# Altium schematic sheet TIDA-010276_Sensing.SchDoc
size 431 x 279 mm; Date: Not shown in title block; ApprovedBy: Not shown in title block; CheckedBy: Not shown in title block; Author: Not shown in title block; CompanyName: Not shown in title block; DrawnBy: Jenson Fang; Engineer: Jenson Fang; Organization: Not shown in title block; Address1: Not shown in title block; Address2: Not shown in title block; Address3: Not shown in title block; Address4: Not shown in title block; DocumentNumber: 1; Revision: Use project parameter SCH_Rev; SheetNumber: 4; SheetTotal: 6; PageSetup: Record=PageOptions¦CenterHorizontal=True¦CenterVertical=True¦PrintScale=1.00¦XCorrection=1.00¦YCorrection=1.00¦PrintKind=0¦BorderSize=5000000¦LeftOffset=0¦BottomOffset=0¦Orientation=2¦PaperLength=1000¦PaperWidth=1000¦Scale=100¦PaperSource=15¦PrintQuality=600¦MediaType=1¦DitherType=10¦PaperKind=Letter¦PrintScaleMode=1
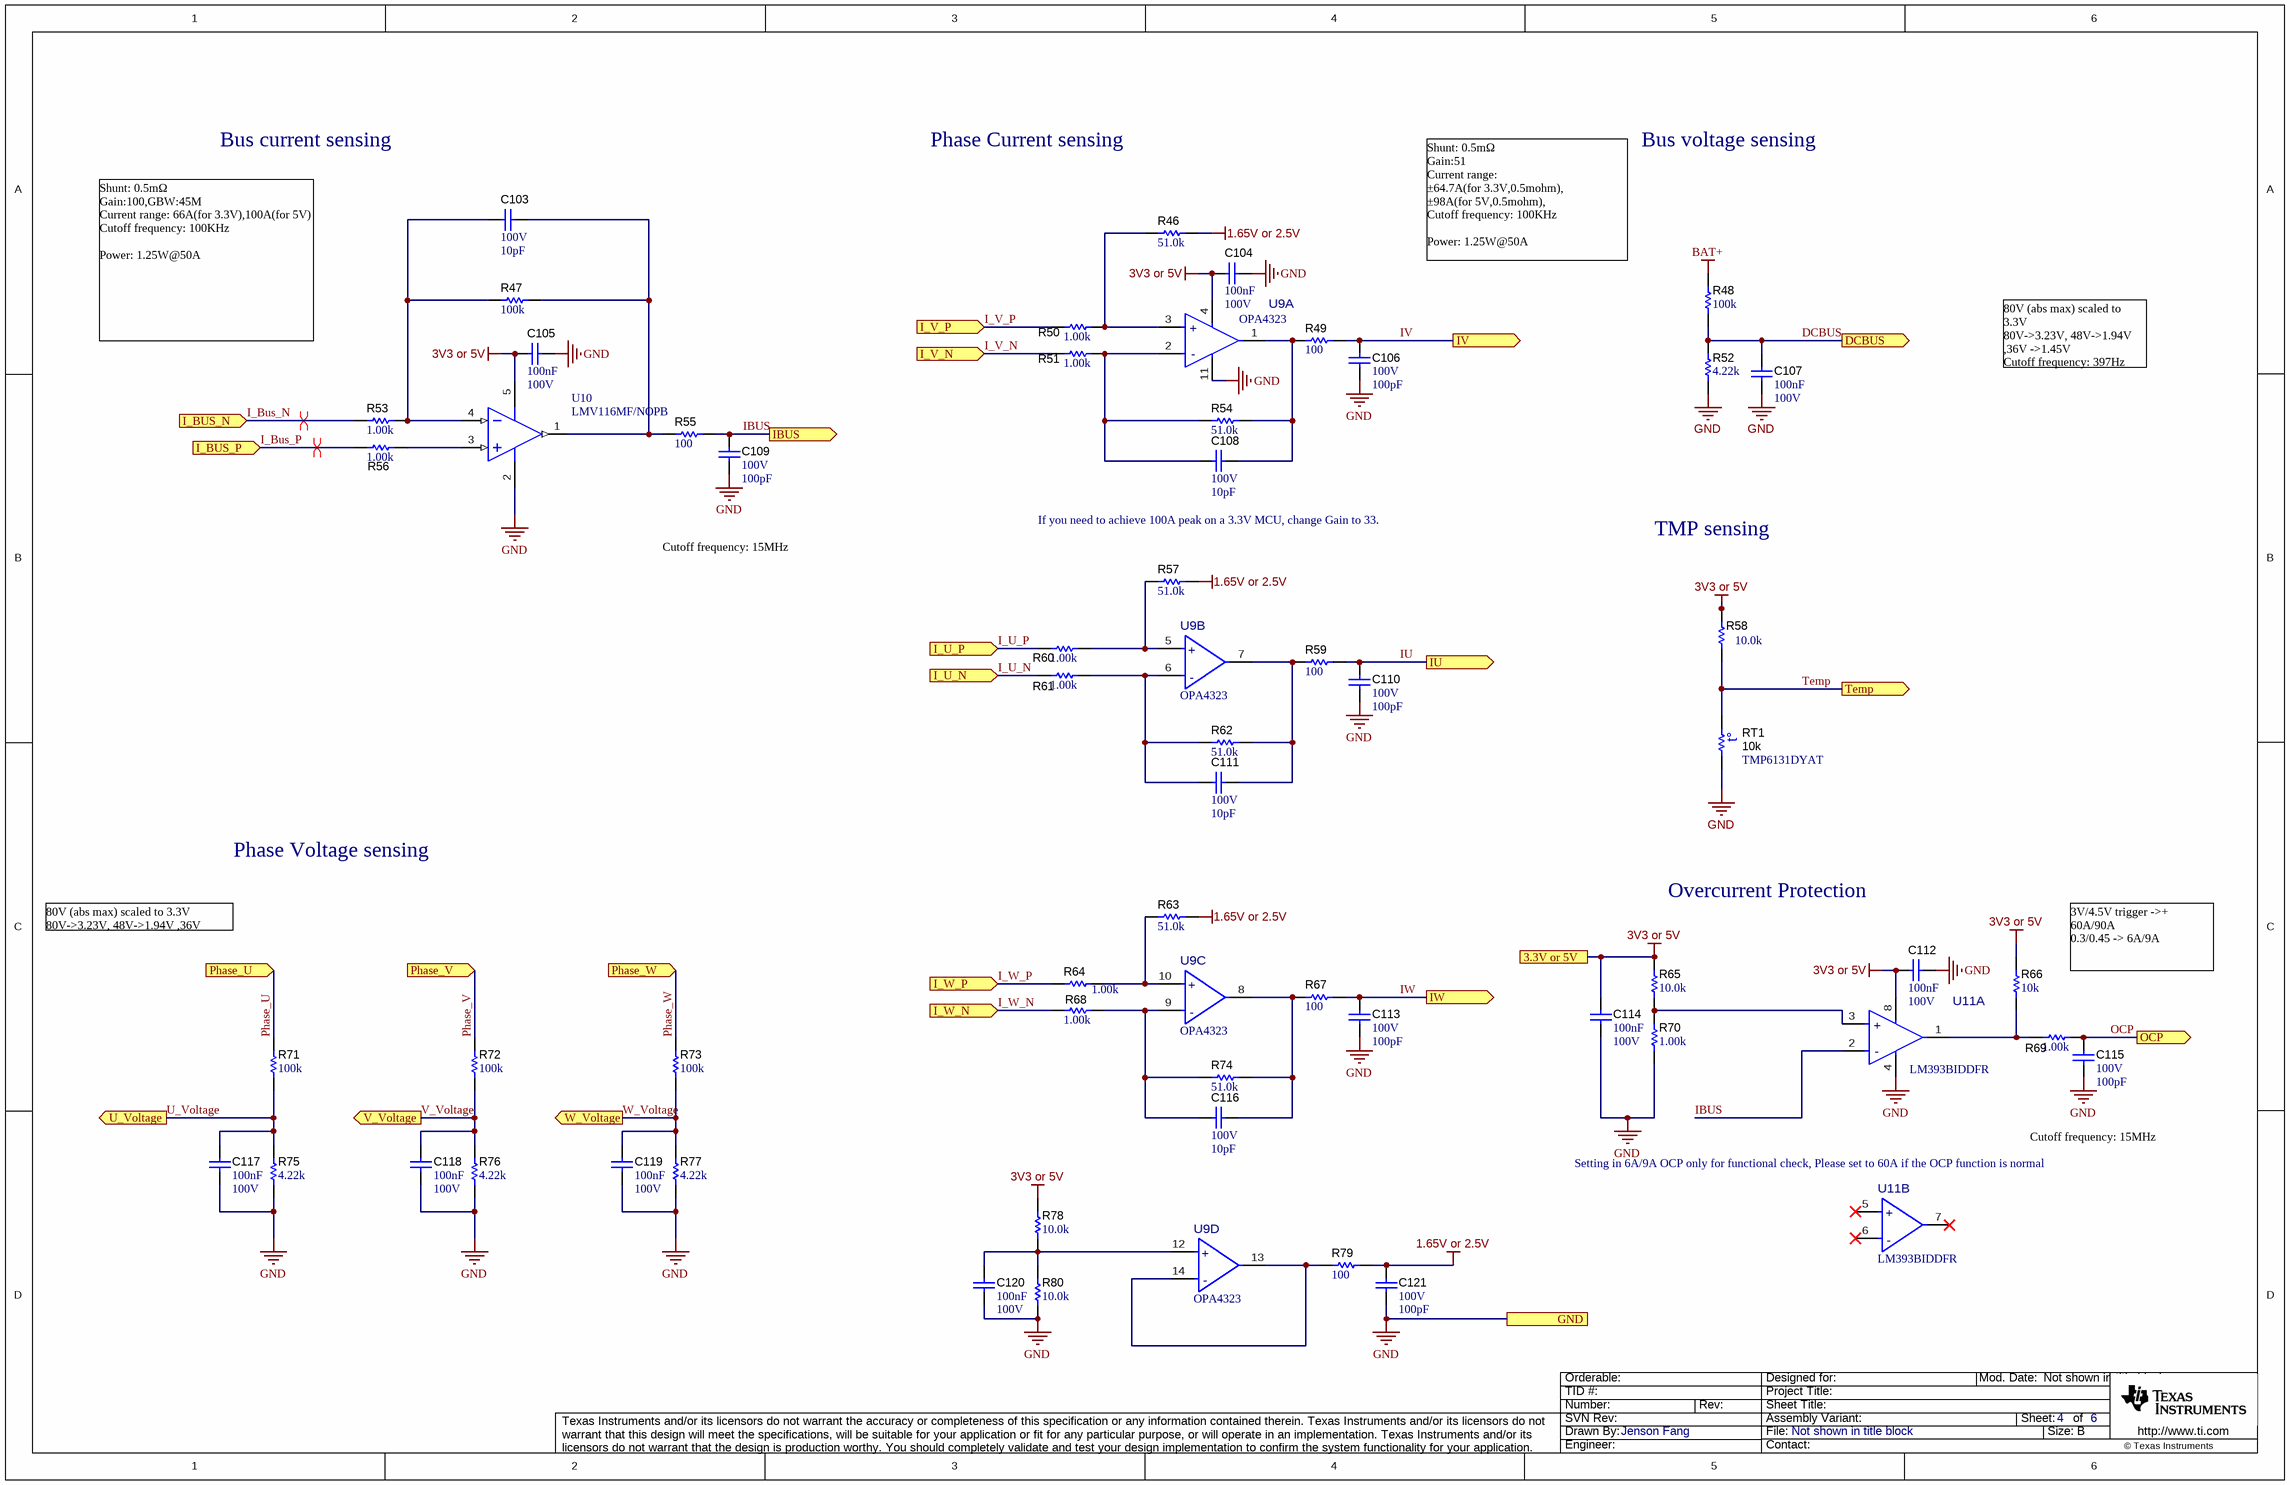
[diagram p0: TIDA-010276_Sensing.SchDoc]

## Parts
C103  VDC_V: 100V  ValueDisplayed: 10pF  [0603]  (hidden comment: GRM1885C2A100JA01D)
C104  Cap_F: 100nF  VDC_V: 100V  [0603]  (hidden comment: GRM188R72A104KA35D)
C105  Cap_F: 100nF  VDC_V: 100V  [0603]  (hidden comment: GRM188R72A104KA35D)
C106  VDC_V: 100V  ValueDisplayed: 100pF  [0603]  (hidden comment: GRM1885C2A101JA01D)
C107  Cap_F: 100nF  VDC_V: 100V  [0603]  (hidden comment: GRM188R72A104KA35D)
C108  VDC_V: 100V  ValueDisplayed: 10pF  [0603]  (hidden comment: GRM1885C2A100JA01D)
C109  VDC_V: 100V  ValueDisplayed: 100pF  [0603]  (hidden comment: GRM1885C2A101JA01D)
C110  VDC_V: 100V  ValueDisplayed: 100pF  [0603]  (hidden comment: GRM1885C2A101JA01D)
C111  VDC_V: 100V  ValueDisplayed: 10pF  [0603]  (hidden comment: GRM1885C2A100JA01D)
C112  Cap_F: 100nF  VDC_V: 100V  [0603]  (hidden comment: GRM188R72A104KA35D)
C113  VDC_V: 100V  ValueDisplayed: 100pF  [0603]  (hidden comment: GRM1885C2A101JA01D)
C114  Cap_F: 100nF  VDC_V: 100V  [0603]  (hidden comment: GRM188R72A104KA35D)
C115  VDC_V: 100V  ValueDisplayed: 100pF  [0603]  (hidden comment: GRM1885C2A101JA01D)
C116  VDC_V: 100V  ValueDisplayed: 10pF  [0603]  (hidden comment: GRM1885C2A100JA01D)
C117  Cap_F: 100nF  VDC_V: 100V  [0603]  (hidden comment: GRM188R72A104KA35D)
C118  Cap_F: 100nF  VDC_V: 100V  [0603]  (hidden comment: GRM188R72A104KA35D)
C119  Cap_F: 100nF  VDC_V: 100V  [0603]  (hidden comment: GRM188R72A104KA35D)
C120  Cap_F: 100nF  VDC_V: 100V  [0603]  (hidden comment: GRM188R72A104KA35D)
C121  VDC_V: 100V  ValueDisplayed: 100pF  [0603]  (hidden comment: GRM1885C2A101JA01D)
R46  ValueDisplayed: 51.0k  [0603]  (hidden comment: RC0603FR-0751KL)
R47  ValueDisplayed: 100k  [0603]  (hidden comment: CRCW0603100KJNEAC)
R48  ValueDisplayed: 100k  [0603]  (hidden comment: CRCW0603100KFKEA)
R49  ValueDisplayed: 100  [0603]  (hidden comment: CRCW0603100RFKEA)
R50  ValueDisplayed: 1.00k  [0603]  (hidden comment: CRCW06031K00FKEA)
R51  ValueDisplayed: 1.00k  [0603]  (hidden comment: CRCW06031K00FKEA)
R52  ValueDisplayed: 4.22k  [0603]  (hidden comment: RC0603FR-074K22L)
R53  ValueDisplayed: 1.00k  [0603]  (hidden comment: CRCW06031K00FKEA)
R54  ValueDisplayed: 51.0k  [0603]  (hidden comment: RC0603FR-0751KL)
R55  ValueDisplayed: 100  [0603]  (hidden comment: CRCW0603100RFKEA)
R56  ValueDisplayed: 1.00k  [0603]  (hidden comment: CRCW06031K00FKEA)
R57  ValueDisplayed: 51.0k  [0603]  (hidden comment: RC0603FR-0751KL)
R58  ValueDisplayed: 10.0k  [0603]  (hidden comment: CRCW060310K0FKEA)
R59  ValueDisplayed: 100  [0603]  (hidden comment: CRCW0603100RFKEA)
R60  ValueDisplayed: 1.00k  [0603]  (hidden comment: CRCW06031K00FKEA)
R61  ValueDisplayed: 1.00k  [0603]  (hidden comment: CRCW06031K00FKEA)
R62  ValueDisplayed: 51.0k  [0603]  (hidden comment: RC0603FR-0751KL)
R63  ValueDisplayed: 51.0k  [0603]  (hidden comment: RC0603FR-0751KL)
R64  ValueDisplayed: 1.00k  [0603]  (hidden comment: CRCW06031K00FKEA)
R65  ValueDisplayed: 10.0k  [0603]  (hidden comment: CRCW060310K0FKEA)
R66  ValueDisplayed: 10k  [0603]  (hidden comment: CRCW060310K0JNEA)
R67  ValueDisplayed: 100  [0603]  (hidden comment: CRCW0603100RFKEA)
R68  ValueDisplayed: 1.00k  [0603]  (hidden comment: CRCW06031K00FKEA)
R69  ValueDisplayed: 1.00k  [0603]  (hidden comment: CRCW06031K00FKEA)
R70  ValueDisplayed: 1.00k  [0603]  (hidden comment: CRCW06031K00FKEA)
R71  ValueDisplayed: 100k  [0603]  (hidden comment: CRCW0603100KFKEA)
R72  ValueDisplayed: 100k  [0603]  (hidden comment: CRCW0603100KFKEA)
R73  ValueDisplayed: 100k  [0603]  (hidden comment: CRCW0603100KFKEA)
R74  ValueDisplayed: 51.0k  [0603]  (hidden comment: RC0603FR-0751KL)
R75  ValueDisplayed: 4.22k  [0603]  (hidden comment: RC0603FR-074K22L)
R76  ValueDisplayed: 4.22k  [0603]  (hidden comment: RC0603FR-074K22L)
R77  ValueDisplayed: 4.22k  [0603]  (hidden comment: RC0603FR-074K22L)
R78  ValueDisplayed: 10.0k  [0603]  (hidden comment: CRCW060310K0FKEA)
R79  ValueDisplayed: 100  [0603]  (hidden comment: CRCW0603100RFKEA)
R80  ValueDisplayed: 10.0k  [0603]  (hidden comment: CRCW060310K0FKEA)
RT1  value 10k  [DYA0002A-MFG]  (hidden comment: TMP6131DYAT)
U9  OPA4323  [PW0014A-MFG]  (parts A,B,C,D of 4)
U10  LMV116MF/NOPB  [DBV0005A_N]
U11  LM393BIDDFR  [DDF0008A-MFG]  (parts A,B of 2)

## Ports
3.3V or 5V, DCBUS (out), GND, I_BUS_N (in), I_BUS_P (in), I_U_N (in), I_U_P (in), I_V_N (in), I_V_P (in), I_W_N (in), I_W_P (in), IBUS (out), IU (out), IV (out), IW (out), OCP (out), Phase_U (in), Phase_V (in), Phase_W (in), Temp (out), U_Voltage (out), V_Voltage (out), W_Voltage (out)

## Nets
1.65V or 2.5V: C121.1 R46.2 R57.2 R63.2 R79.2
3V3 or 5V: C104.2 C105.2 C112.2 C114.1 R58.2 R65.2 R66.2 R78.2 U9.4(V+) U10.5(V+) U11.8(VCC) ; port 3.3V or 5V
BAT+: R48.2
GND: C104.1 C105.1 C106.2 C107.2 C109.2 C110.2 C112.1 C113.2 C114.2 C115.2 C117.2 C118.2 C119.2 C120.2 C121.2 R52.1 R70.1 R75.1 R76.1 R77.1 R80.1 RT1.1 U9.11(V-) U10.2(V-) U11.4(GND) ; port GND
DCBUS: C107.1 R48.1 R52.2 ; port DCBUS
I_Bus_N: R53.1 ; port I_BUS_N
I_Bus_P: R56.1 ; port I_BUS_P
I_U_N: R61.2 ; port I_U_N
I_U_P: R60.1 ; port I_U_P
I_V_N: R51.1 ; port I_V_N
I_V_P: R50.1 ; port I_V_P
I_W_N: R68.1 ; port I_W_N
I_W_P: R64.1 ; port I_W_P
IBUS: C109.1 R55.2 U11.2(1IN-) ; port IBUS
IU: C110.1 R59.2 ; port IU
IV: C106.1 R49.2 ; port IV
IW: C113.1 R67.2 ; port IW
OCP: C115.1 R69.1 ; port OCP
Phase_U: R71.2 ; port Phase_U
Phase_V: R72.2 ; port Phase_V
Phase_W: R73.2 ; port Phase_W
Temp: R58.1 RT1.2 ; port Temp
U_Voltage: C117.1 R71.1 R75.2 ; port U_Voltage
V_Voltage: C118.1 R72.1 R76.2 ; port V_Voltage
W_Voltage: C119.1 R73.1 R77.2 ; port W_Voltage
NetC103_1: C103.1 R47.2 R55.1 U10.1(OUT)
NetC103_2: C103.2 R47.1 R53.2 U10.4(IN-)
NetC108_1: C108.1 R49.1 R54.2 U9.1(OUT1)
NetC108_2: C108.2 R51.2 R54.1 U9.2(IN1-)
NetC111_1: C111.1 R59.1 R62.2 U9.7(OUT2)
NetC111_2: C111.2 R61.1 R62.1 U9.6(IN2-)
NetC116_1: C116.1 R67.1 R74.2 U9.8(OUT3)
NetC116_2: C116.2 R68.2 R74.1 U9.9(IN3-)
NetC120_1: C120.1 R78.1 R80.2 U9.12(IN4+)
NetR46_1: R46.1 R50.2 U9.3(IN1+)
NetR56_2: R56.2 U10.3(IN+)
NetR57_1: R57.1 R60.2 U9.5(IN2+)
NetR63_1: R63.1 R64.2 U9.10(IN3+)
NetR65_1: R65.1 R70.2 U11.3(1IN+)
NetR66_1: R66.1 R69.2 U11.1(1OUT)
NetR79_1: R79.1 U9.13(IN4-) U9.14(OUT4)

Not connected (* = marked no-connect by the designer): U11 5(2IN+)* 6(2IN-)* 7(2OUT)*

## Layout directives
differential pair: I_Bus_N, I_Bus_P

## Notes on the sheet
- Bus current sensing
- Phase Current sensing
- Bus voltage sensing
- Shunt: 0.5mΩ
  Gain:51
  Current range:
  ±64.7A(for 3.3V,0.5mohm),
  ±98A(for 5V,0.5mohm),
  Cutoff frequency: 100KHz
  Power: 1.25W@50A
- Shunt: 0.5mΩ
  Gain:100,GBW:45M
  Current range: 66A(for 3.3V),100A(for 5V)
  Cutoff frequency: 100KHz
  Power: 1.25W@50A
- 80V (abs max) scaled to 3.3V
  80V->3.23V, 48V->1.94V ,36V ->1.45V
  Cutoff frequency: 397Hz
- Cutoff frequency: 15MHz
- If you need to achieve 100A peak on a 3.3V MCU, change Gain to 33.
- TMP sensing
- Phase Voltage sensing
- Overcurrent Protection
- 80V (abs max) scaled to 3.3V
  80V->3.23V, 48V->1.94V ,36V ->1.45V
  output= input voltage * Dudy * 0.0404
- 3V/4.5V trigger ->+ 60A/90A
  0.3/0.45 -> 6A/9A
- (near U11) Setting in 6A/9A OCP only for functional check, Please set to 60A if the OCP function is normal

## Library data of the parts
C103 C108 C111 C116 = CMP-0007236-3: CAP, CERM, 10 pF, 100 V, +/- 5%, C0G/NP0, 0603; Manufacturer: MuRata; TaMin_C: -55°C; Polarized: N; SizeAreaWB_mm2: 4.68; Value1: Unknown; U/M: EA; Value: 10pF; TaMax_C: 125°C; SizeZ_mm: 1; SizeX_mm: 1.6; SizeY_mm: 0.8; SizeArea_mm2: 1.28; AEC Category: Q200
C104 C105 C107 C112 C114 C117-C120 = CMP-0007469-4: CAP, CERM, 0.1 uF, 100 V, +/- 10%, X7R, 0603; Manufacturer: MuRata; TaMin_C: -55°C; Polarized: N; SizeAreaWB_mm2: 4.68; Value1: Unknown; U/M: EA; Value: 0.1uF; TaMax_C: 125°C; SizeZ_mm: 1; SizeX_mm: 1.6; SizeY_mm: 0.8; SizeArea_mm2: 1.28; AEC Category: Q200
C106 C109 C110 C113 C115 C121 = CMP-0007237-4: CAP, CERM, 100 pF, 100 V, +/- 5%, C0G/NP0, 0603; Manufacturer: MuRata; TaMin_C: -55°C; Polarized: N; SizeAreaWB_mm2: 4.68; Value1: Unknown; U/M: EA; Value: 100pF; TaMax_C: 125°C; SizeZ_mm: 1; SizeX_mm: 1.6; SizeY_mm: 0.8; SizeArea_mm2: 1.28; AEC Category: Q200
R46 R54 R57 R62 R63 R74 = CMP-0023167-5: RES, 51.0 k, 1%, 0.1 W, 0603; Manufacturer: Yageo; Power_W: 100mW; TempCo: 100 ppm/C; Value_Code: 51k0; Value: 51.0k; Res_ohm: 51k; SizeX_mm: 1.6; SizeY_mm: 0.8; SizeZ_mm: 1; Value2: 0.1W; SizeArea_mm2: 1.28; AEC Qualified: N; VDC_V: 75V; AEC Category: Q200; SizeAreaWB_mm2: 4.68
R47 = CMP-0082530-1: RES, 100 k, 5%, 0.1 W, 0603; Manufacturer: Vishay-Dale; Power_W: 100mW; TempCo: 200 ppm/C; SizeAreaWB_mm2: 4.68; Value: 100k; EIA_Code: E24; SizeX_mm: 1.6; SizeY_mm: 0.8; SizeZ_mm: 1; Value2: 0.1W; SizeArea_mm2: 1.28; AEC Qualified: N; VDC_V: 75V; AEC Category: Q200
R48 R71-R73 = CMP-0021990-1: RES, 100 k, 1%, 0.1 W, 0603; Manufacturer: Vishay-Dale; Power_W: 100mW; TempCo: 100 ppm/C; U/M: EA; Value: 100k; EIA_Code: E96; SizeX_mm: 1.6; SizeY_mm: 0.8; SizeZ_mm: 1; Value2: 0.1W; SizeArea_mm2: 1.28; VDC_V: 75V; AEC Category: Q200
R49 R55 R59 R67 R79 = CMP-0021991-4: RES, 100, 1%, 0.1 W, AEC-Q200 Grade 0, 0603; Manufacturer: Vishay-Dale; Power_W: 100mW; TempCo: 100 ppm/C; Value_Code: 100R; Value: 100; EIA_Code: E96; SizeX_mm: 1.6; SizeY_mm: 0.8; SizeZ_mm: 1; Value2: 0.1W; SizeArea_mm2: 1.28; AEC Qualified: Y; VDC_V: 75V; AEC Category: Q200; AEC Grade: 0
R50 R51 R53 R56 R60 R61 R64 R68-R70 = CMP-0022109-2: RES, 1.00 k, 1%, 0.1 W, 0603; Manufacturer: Vishay-Dale; Power_W: 100mW; TempCo: 100 ppm/C; Value_Code: 1k00; U/M: EA; Value: 1.00k; EIA_Code: E96; Res_ohm: 1k; SizeX_mm: 1.6; SizeY_mm: 0.8; SizeZ_mm: 1; Value2: 0.1W; SizeArea_mm2: 1.28; VDC_V: 75V; AEC Category: Q200
R52 R75-R77 = CMP-0023146-5: RES, 4.22 k, 1%, 0.1 W, 0603; Manufacturer: Yageo; Power_W: 100mW; TempCo: 100 ppm/C; Value_Code: 4k22; Value: 4.22k; EIA_Code: E96; SizeX_mm: 1.6; SizeY_mm: 0.8; SizeZ_mm: 1; Value2: 0.1W; SizeArea_mm2: 1.28; AEC Qualified: N; VDC_V: 75V; AEC Category: Q200; SizeAreaWB_mm2: 4.68
R58 R65 R78 R80 = CMP-0021998-2: RES, 10.0 k, 1%, 0.1 W, 0603; Manufacturer: Vishay-Dale; Power_W: 100mW; TempCo: 100 ppm/C; Value_Code: 10k0; U/M: EA; Value: 10.0k; EIA_Code: E96; Res_ohm: 10k; SizeX_mm: 1.6; SizeY_mm: 0.8; SizeZ_mm: 1; Value2: 0.1W; SizeArea_mm2: 1.28; VDC_V: 75V; AEC Category: Q200
R66 = CMP-0025701-4: RES, 10 k, 5%, 0.1 W, AEC-Q200 Grade 0, 0603; Manufacturer: Vishay-Dale; Power_W: 100mW; TempCo: 200 ppm/C; Value_Code: 10k0; Value: 10k; EIA_Code: E24; SizeX_mm: 1.6; SizeY_mm: 0.8; SizeZ_mm: 1; Value2: 0.1W; SizeArea_mm2: 1.28; AEC Qualified: Y; VDC_V: 75V; AEC Category: Q200; AEC Grade: 0
RT1 = CMP-0091865-2: ±1% tolerance 10kΩ linear thermistor available in 0402 and 0603 package options 2-SOT-5X3 -40 to 125; Manufacturer: Texas Instruments; Max Current: 400uA; AEC Qualified: No; TJmax_C: +155°C; TaMin_C: -40°C; TempCo: 6400ppm/°C; TaMax_C: +125°C; VDC_V: 5.5V; SizeZ_mm: 0.77mm; AEC Category: Q200; CompType: IC
U9 = CMP-0121081-1: 20 MHz High Bandwidth, 100 dB CMRR, Low Voltage (1.7 V to 5.5 V), RRIO Zero-Cross Operational Amplifier; Manufacturer: Texas Instruments; SizeZ_mm: 1.2mm; AEC Qualified: No; Gain Bandwidth: 20MHz; Input Bias Current: 0.0000005uA; Input Offset Voltage: 0.15mV; Max Dual Supply Voltage: 2.75V; Max Supply Voltage: 5.5V; Min Dual Supply Voltage: 850mV; Min Supply Voltage: 1.7V; Nominal Supply Current: 1.6mA; Number Of Channels: 4; Output Current Per Channel: 110mA; Response Time: 250ns; Standoff Height: 0.05mm; TaMax_C: +125°C; TaMin_C: -40°C; TJmax_C: +150°C; Voltage Gain: 120dB
U10 = CMP-0068461-2: Low Voltage, 45MHz, Rail-to-Rail Output Operational Amplifiers with Shutdown Option, DBV0005A (SOT-23-5); Manufacturer: Texas Instruments; CompType: IC; AEC Category: Q200; AEC Qualified: N; Rating: Catalog; SizeAreaWB_mm2: 14.82; SizeArea_mm2: 8.12; SizeX_mm: 2.8; SizeY_mm: 2.9; SizeZ_mm: 1.45
U11 = CMP-0089113-1: Dual Comparator SOT23-8; Manufacturer: Texas Instruments; Output Current Per Channel: 21mA; TaMin_C: -40°C; Input Bias Current: -0.0035uA; Min Supply Voltage: 3V; Response Time: 1000ns; TJmax_C: +150°C; SizeZ_mm: 1.1mm; Number Of Channels: 2; Max Supply Voltage: 36V; TaMax_C: +85°C; Input Offset Voltage: 0.37mV; Voltage Gain: 200V/mV; Standoff Height: 0mm; AEC Qualified: No; Nominal Supply Current: 400-550uA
